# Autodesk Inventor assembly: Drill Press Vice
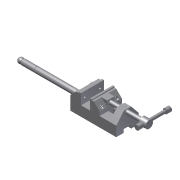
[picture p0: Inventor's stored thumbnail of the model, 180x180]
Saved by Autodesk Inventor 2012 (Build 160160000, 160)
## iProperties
Created: 2009-05
Part Number: Drill Press Vice
Document SubType Name: Assembly
Designer: Sham
Author: Sham
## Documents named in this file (9)
- C:\Users\CadCim\Documents\SAILESH\inventor-2011-fact-prt\c1211inv_2012-prt\c12_inv_2012_prt\Tutorials\c12_tut03_inv\Drill Press Vice.iam
- C:\Users\CadCim\Documents\SAILESH\inventor-2011-fact-prt\c1211inv_2012-prt\Tutorials\c12-tut03-inv\Base.ipt
- C:\Users\CadCim\Documents\SAILESH\inventor-2011-fact-prt\c1211inv_2012-prt\Tutorials\c12-tut03-inv\Safety Handle.ipt
- C:\Users\CadCim\Documents\SAILESH\inventor-2011-fact-prt\c1211inv_2012-prt\Tutorials\c12-tut03-inv\Jaw Face.ipt
- C:\Users\CadCim\Documents\SAILESH\inventor-2011-fact-prt\c1211inv_2012-prt\Tutorials\c12-tut03-inv\Movable Jaw.ipt
- C:\Users\CadCim\Documents\SAILESH\inventor-2011-fact-prt\c1211inv_2012-prt\Tutorials\c12-tut03-inv\Cap Screw.ipt
- C:\Users\CadCim\Documents\SAILESH\inventor-2011-fact-prt\c1211inv_2012-prt\Tutorials\c12-tut03-inv\Clamp Screw Handle.ipt
- C:\Users\CadCim\Documents\SAILESH\inventor-2011-fact-prt\c1211inv_2012-prt\Tutorials\c12-tut03-inv\Clamp Screw.ipt
- C:\Users\CadCim\Documents\SAILESH\inventor-2011-fact-prt\c1211inv_2012-prt\Tutorials\c12-tut03-inv\Handle Stop.ipt
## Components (13 placed, 8 different names)
1. Base:1 — Mate:2, Mate:3, Mate:7, Insert:10, Insert:11, Insert:12, Insert:13
2. Safety Handle:1
3. Jaw Face:1 — Insert:8, Insert:9, Mate:7
4. Jaw Face:2 — Insert:10, Insert:11
5. Movable Jaw:1 — Mate:2, Mate:3, Insert:2, Insert:3, Insert:4, Insert:8, Insert:9
6. Cap Screw:1 — Insert:2
7. Cap Screw:2 — Insert:3
8. Cap Screw:3 — Insert:13
9. Cap Screw:4 — Insert:12
10. Clamp Screw:1 — Insert:4, Mate:6, Rotation/Translation:2
11. Clamp Screw Handle:1 — Mate:6, Insert:5, Insert:6, Rotation/Translation:2
12. Handle Stop:1 — Insert:6, Mate:8
13. Handle Stop:2 — Insert:5
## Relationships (17: Insert 11, Mate 5, RelateRotateTranslate 1)
- Mate:2: Base:1 ↔ Movable Jaw:1
- Mate:3: Base:1 ↔ Movable Jaw:1
- Insert:2: Movable Jaw:1 ↔ Cap Screw:1
- Insert:3: Movable Jaw:1 ↔ Cap Screw:2
- Insert:4: Movable Jaw:1 ↔ Clamp Screw:1
- Mate:6: Clamp Screw:1 ↔ Clamp Screw Handle:1
- Insert:5: Clamp Screw Handle:1 ↔ Handle Stop:2
- Insert:6: Clamp Screw Handle:1 ↔ Handle Stop:1
- Insert:8: Jaw Face:1 ↔ Movable Jaw:1
- Insert:9: Jaw Face:1 ↔ Movable Jaw:1
- Mate:7: Base:1 ↔ Jaw Face:1
- Rotation/Translation:2 [RelateRotateTranslate]: Clamp Screw:1 ↔ Clamp Screw Handle:1
- Mate:8: Handle Stop:1
- Insert:10: Base:1 ↔ Jaw Face:2
- Insert:11: Base:1 ↔ Jaw Face:2
- Insert:12: Base:1 ↔ Cap Screw:4
- Insert:13: Base:1 ↔ Cap Screw:3
